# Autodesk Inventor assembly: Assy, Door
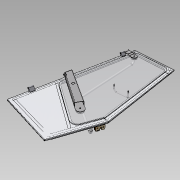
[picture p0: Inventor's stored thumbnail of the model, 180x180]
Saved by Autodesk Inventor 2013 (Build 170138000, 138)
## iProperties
Shininess: 64.0
Length Units: 11269
Angle Units: 11279
Time Units: 11290
Mass Units: 11283
Length Display Precision: 3
Angle Display Precision: 2
Compacted: True
Created: 2005-02
Part Number: Assy, Door
Document SubType Name: Assembly
Designer: =<Author>
Manufacturer: Standard
Standards Organization: Custom
Description: Left door
Density: 0.0
Volumn: 0.0
Area: 0.0
PropertySet Name: Model Information
Control State: 0
Master: False
Checked Out: False
Author: PVitaliy
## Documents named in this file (7)
- Y:\Dropbox\Launch 2013\Eco Material Advisor\Assy, Door\_Data\Assy, Cab\Assy, Door.iam
- Y:\Dropbox\Launch 2013\Eco Material Advisor\Assy, Door\_Data\Assy, Cab\PK46.51.11.015.ipt
- Y:\Dropbox\Launch 2013\Eco Material Advisor\Assy, Door\_Data\Assy, Cab\integral hinge.ipt
- Y:\Dropbox\Launch 2013\Eco Material Advisor\Assy, Door\_Data\Assy, Cab\PK46.51.11.040.ipt
- Y:\Dropbox\Launch 2013\Eco Material Advisor\Assy, Door\_Data\Assy, Cab\2108-6105015.ipt
- Y:\Dropbox\Launch 2013\Eco Material Advisor\Assy, Door\_Data\Assy, Cab\Frame, Door.ipt
- Y:\Dropbox\Launch 2013\Eco Material Advisor\Assy, Door\_Data\Assy, Cab\Assy, Sub-Door.iam
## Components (7 placed, 6 different names)
1. Frame, Door:2 — Mate:39, Mate:40, Mate:41, Mate:42, Mate:43, Flush:24, Mate:44, Mate:45, Tangent:1, Tangent:2, Angle:1
2. PK46.51.11.015:1 — Mate:45, Tangent:1, Tangent:2, Angle:1
3. PK46.51.11.040:2 — Mate:39, Mate:40, Mate:41, Mate:46, Angle:2, Mate:47
4. 2108-6105015:2 — Mate:46, Angle:2, Mate:47
5. integral hinge:1 — Insert:3, Mate:44, Insert:4
6. integral hinge:2 — Mate:42, Mate:43, Flush:24, Insert:3
7. Assy, Sub-Door:1 [sub-assembly] — Insert:4
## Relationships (16: Mate 9, Insert 2, Tangent 2, Angle 2, Flush 1)
- Mate:39: Frame, Door:2 ↔ PK46.51.11.040:2
- Mate:40: Frame, Door:2 ↔ PK46.51.11.040:2
- Mate:41: Frame, Door:2 ↔ PK46.51.11.040:2
- Mate:42: Frame, Door:2 ↔ integral hinge:2
- Mate:43: Frame, Door:2 ↔ integral hinge:2
- Flush:24: Frame, Door:2 ↔ integral hinge:2
- Insert:3: integral hinge:1 ↔ integral hinge:2
- Mate:44: Frame, Door:2 ↔ integral hinge:1
- Mate:45: Frame, Door:2 ↔ PK46.51.11.015:1
- Tangent:1: Frame, Door:2 ↔ PK46.51.11.015:1
- Tangent:2: Frame, Door:2 ↔ PK46.51.11.015:1
- Angle:1: Frame, Door:2 ↔ PK46.51.11.015:1
- Insert:4: integral hinge:1 ↔ Assy, Sub-Door:1
- Mate:46: PK46.51.11.040:2 ↔ 2108-6105015:2
- Angle:2: PK46.51.11.040:2 ↔ 2108-6105015:2
- Mate:47: PK46.51.11.040:2 ↔ 2108-6105015:2
